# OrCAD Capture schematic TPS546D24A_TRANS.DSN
size Custom; title: TPS546D24A 2.95-V to 16-V, 40-A, up to 4× stackable; rev: 1.0; note: Datasheet: SLUSDN0        EVM: SLUUC47
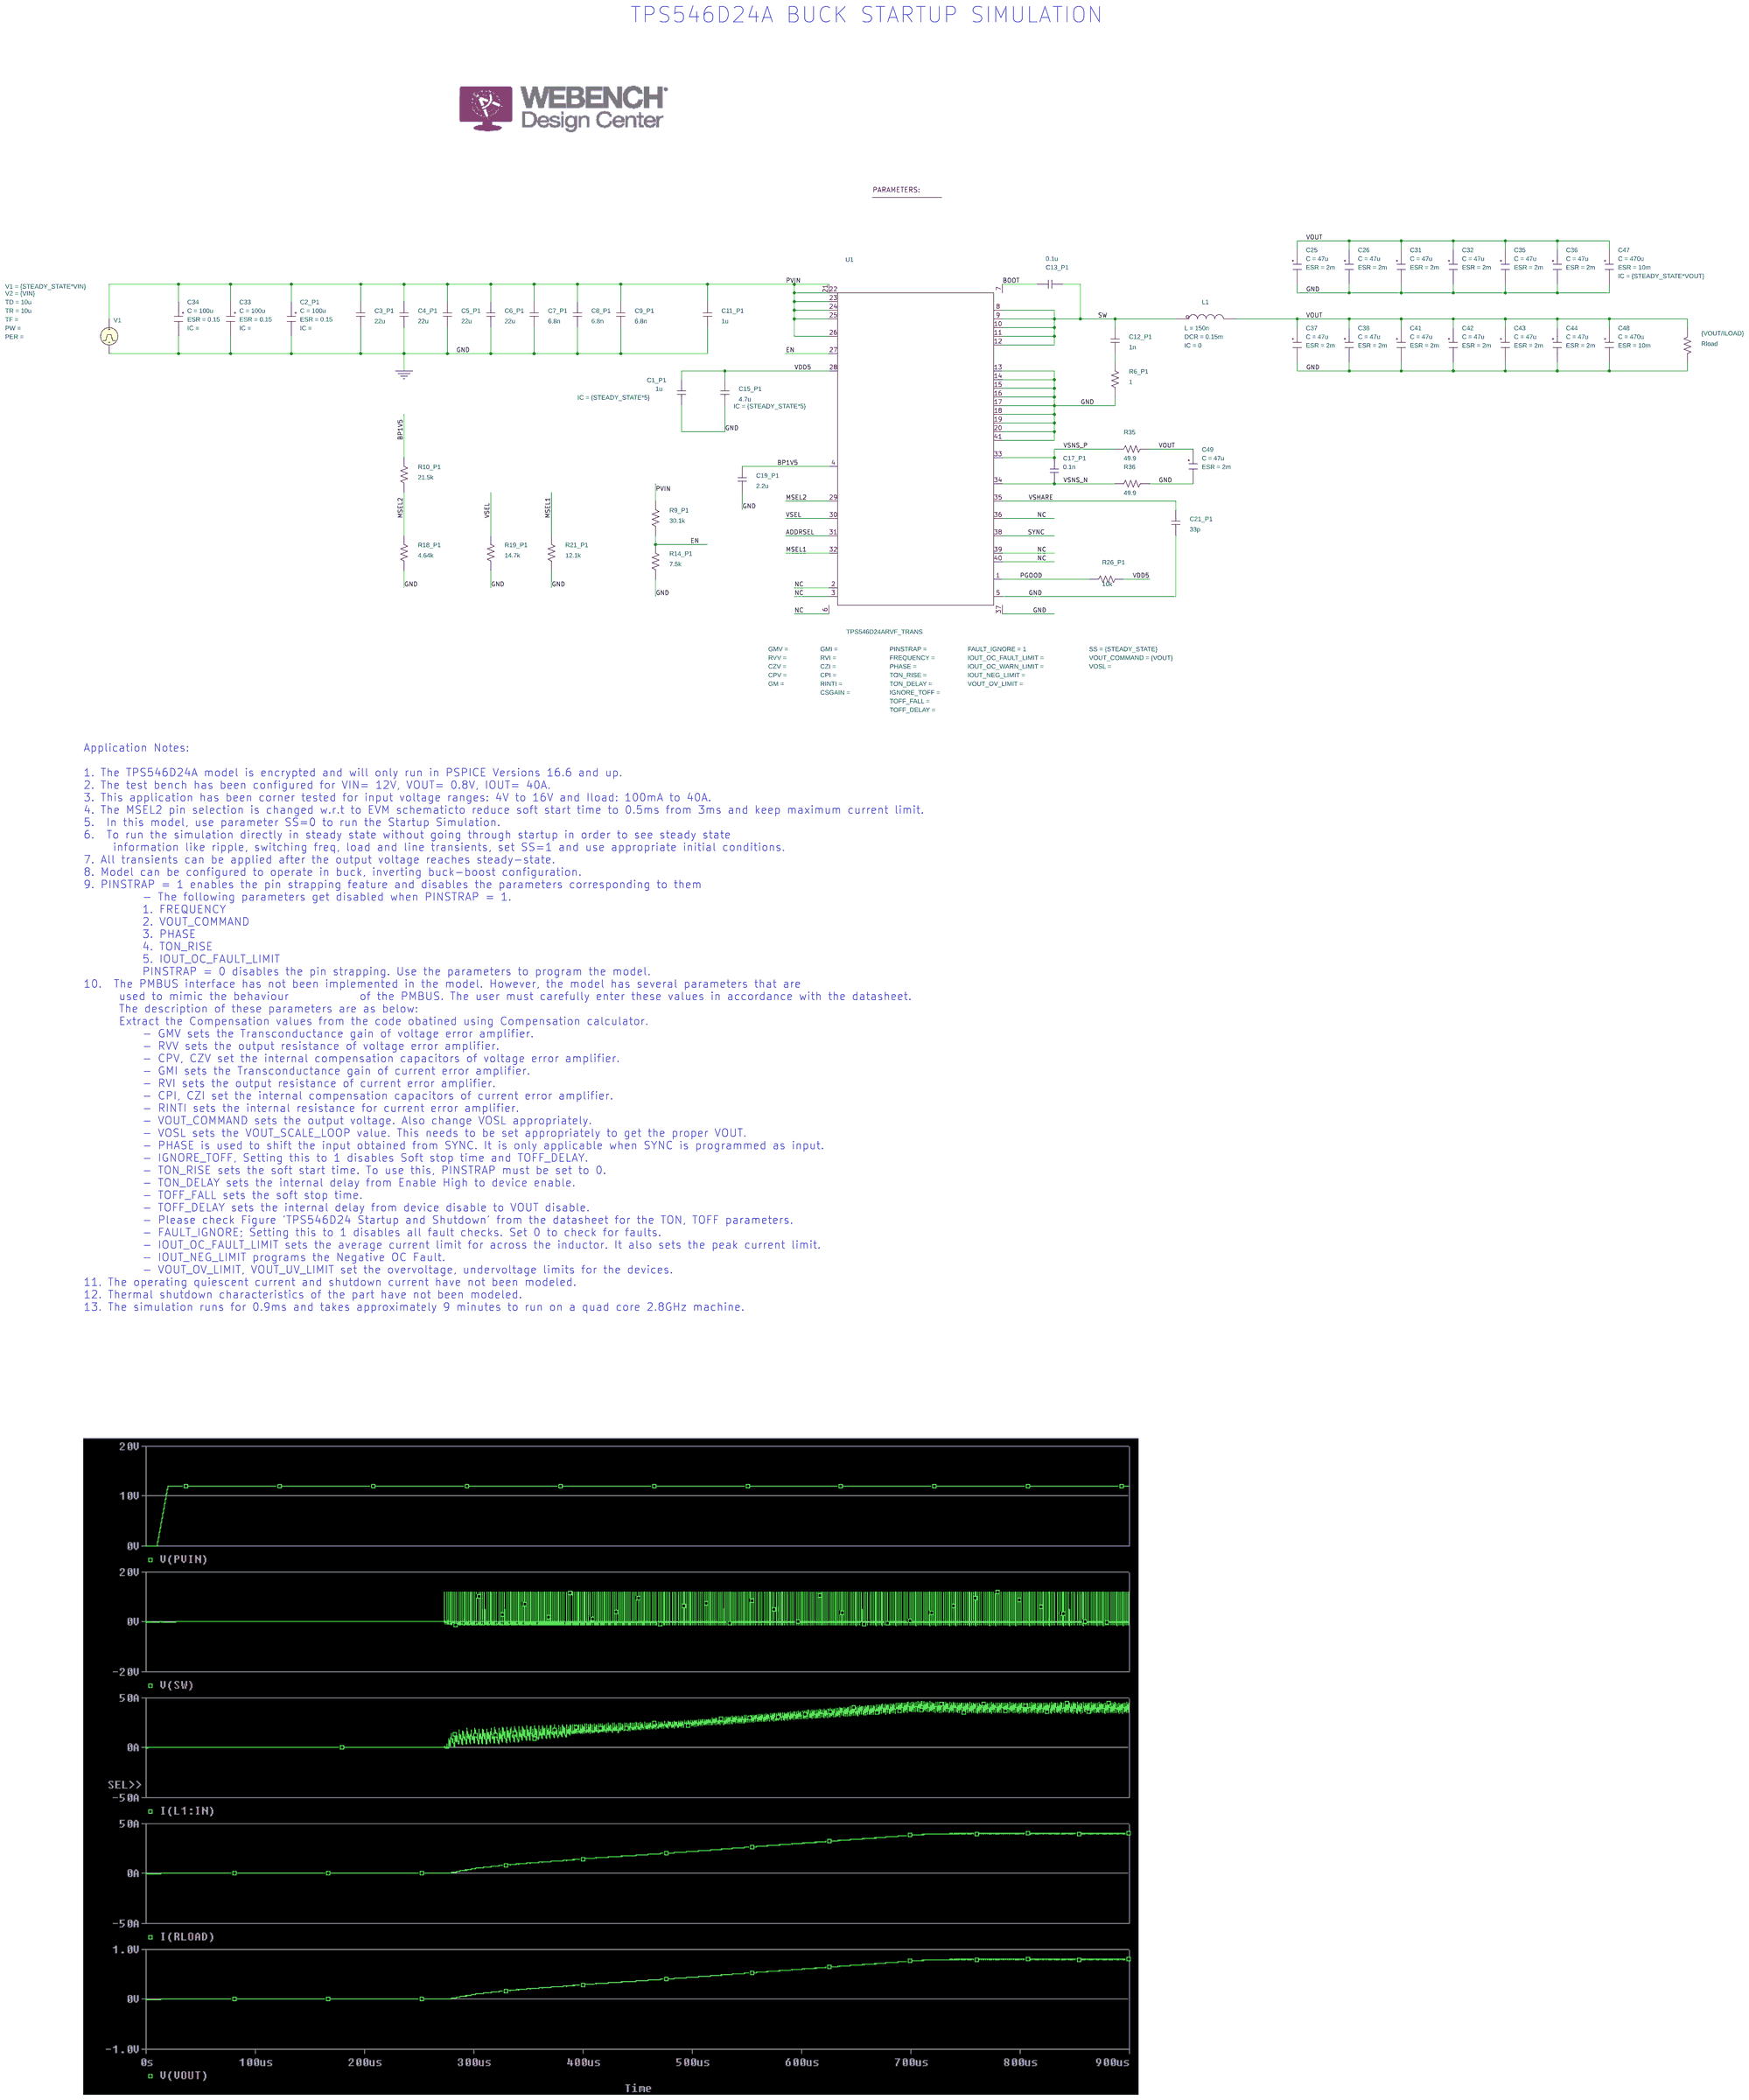
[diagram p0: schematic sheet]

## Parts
1  PARAM
C1_P1  1u  [RAD/CK05]
C2_P1  CESR
C3_P1  22u  [RAD/CK05]
C4_P1  22u  [RAD/CK05]
C5_P1  22u  [RAD/CK05]
C6_P1  22u  [RAD/CK05]
C7_P1  6.8n  [RAD/CK05]
C8_P1  6.8n  [RAD/CK05]
C9_P1  6.8n  [RAD/CK05]
C11_P1  1u  [RAD/CK05]
C12_P1  1n  [RAD/CK05]
C13_P1  0.1u  [RAD/CK05]
C15_P1  4.7u  [RAD/CK05]
C17_P1  0.1n  [RAD/CK05]
C19_P1  2.2u  [RAD/CK05]
C21_P1  33p  [RAD/CK05]
C25  CESR
C26  CESR
C31  CESR
C32  CESR
C33  CESR
C34  CESR
C35  CESR
C36  CESR
C37  CESR
C38  CESR
C41  CESR
C42  CESR
C43  CESR
C44  CESR
C47  CESR
C48  CESR
C49  CESR
L1  LDCR
R6_P1  1  [AX/RC05]
R9_P1  30.1k  [AX/RC05]
R10_P1  21.5k  [AX/RC05]
R14_P1  7.5k  [AX/RC05]
R18_P1  4.64k  [AX/RC05]
R19_P1  14.7k  [AX/RC05]
R21_P1  12.1k  [AX/RC05]
R26_P1  10k  [AX/RC05]
R35  49.9  [AX/RC05]
R36  49.9  [AX/RC05]
Rload  {VOUT/ILOAD}  [AX/RC05]
U1  TPS546D24ARVF_TRANS  [RVF0040A]
V1  VPULSE

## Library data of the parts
1 = PARAM: ILOAD: 40; STEADY_STATE: 0; VIN: 12; VOUT: 0.8
C1_P1 C15_P1 = C: IC: {STEADY_STATE*5}
C2_P1 C33 C34 = CESR_0: C: 100u; ESR: 0.15; PSpiceTemplate: X^@REFDES %IN %OUT @MODEL PARAMS:  ?C|C=@C||C=100u|  ?ESR|ESR=@ESR||ESR=0.01| ?X|X=@X||X=2|  ?IC|IC=@IC||IC=2|; X: 1
C3_P1 C4_P1 C5_P1 C6_P1 C7_P1 C8_P1 C9_P1 C11_P1 C12_P1 C13_P1 C17_P1 C19_P1 C21_P1 = C
C25 C26 C31 C32 C35-C38 C41-C44 C49 = CESR_0: C: 47u; ESR: 2m; IC: {STEADY_STATE*VOUT}; PSpiceTemplate: X^@REFDES %IN %OUT @MODEL PARAMS:  ?C|C=@C||C=100u|  ?ESR|ESR=@ESR||ESR=0.01| ?X|X=@X||X=2|  ?IC|IC=@IC||IC=2|; X: 1
C47 C48 = CESR_0: C: 470u; ESR: 10m; IC: {STEADY_STATE*VOUT}; PSpiceTemplate: X^@REFDES %IN %OUT @MODEL PARAMS:  ?C|C=@C||C=100u|  ?ESR|ESR=@ESR||ESR=0.01| ?X|X=@X||X=2|  ?IC|IC=@IC||IC=2|; X: 1
L1 = LDCR_1: DCR: 0.15m; IC: 0; L: 150n; PSpiceTemplate: X^@REFDES %IN %OUT @MODEL PARAMS:  ?L|L=@L||L=1u|  ?DCR|DCR=@DCR||DCR=0.01|  ?IC|IC=@IC||IC=0|
R6_P1 R9_P1 R10_P1 R14_P1 R18_P1 R19_P1 R21_P1 R26_P1 R35 R36 Rload = R
U1 = TPS546D24ARVF_TRANS: FAULT_IGNORE: 1; SS: {STEADY_STATE}; VOUT_COMMAND: {VOUT}
V1 = VPULSE: TD: 10u; TR: 10u; V1: {STEADY_STATE*VIN}; V2: {VIN}

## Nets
PVIN: C2_P1.1(IN) C3_P1.2 C4_P1.2 C5_P1.2 C6_P1.2 C7_P1.2 C8_P1.2 C9_P1.2 C11_P1.2 C33.1(IN) C34.1(IN) R9_P1.2 U1.21 U1.22 U1.23 U1.24 U1.25 U1.26 V1.1(+)
VDD5: C1_P1.1 C15_P1.2 R26_P1.2 U1.28
0: C1_P1.2 C2_P1.2(OUT) C3_P1.1 C4_P1.1 C5_P1.1 C6_P1.1 C7_P1.1 C8_P1.1 C9_P1.1 C11_P1.1 C15_P1.1 C19_P1.1 C21_P1.1 C25.2(OUT) C26.2(OUT) C31.2(OUT) C32.2(OUT) C33.2(OUT) C34.2(OUT) C35.2(OUT) C36.2(OUT) C37.2(OUT) C38.2(OUT) C41.2(OUT) C42.2(OUT) C43.2(OUT) C44.2(OUT) C47.2(OUT) C48.2(OUT) C49.2(OUT) R6_P1.1 R14_P1.1 R18_P1.1 R19_P1.1 R21_P1.1 R36.1 Rload.2 U1.5 U1.13 U1.14 U1.15 U1.16 U1.17 U1.18 U1.19 U1.20 U1.37 U1.41 V1.2(-)
ADDRSEL: U1.31
BOOT: C13_P1.1 U1.7
BP1V5: C19_P1.2 R10_P1.2 U1.4
EN: R9_P1.1 R14_P1.2 U1.27
MSEL1: R21_P1.2 U1.32
MSEL2: R10_P1.1 R18_P1.2 U1.29
NC: U1.2 U1.3 U1.6 U1.36 U1.39 U1.40
PGOOD: R26_P1.1 U1.1
SW: C12_P1.2 C13_P1.2 L1.1(IN) U1.8 U1.9 U1.10 U1.11 U1.12
SYNC: U1.38
VOUT: C25.1(IN) C26.1(IN) C31.1(IN) C32.1(IN) C35.1(IN) C36.1(IN) C37.1(IN) C38.1(IN) C41.1(IN) C42.1(IN) C43.1(IN) C44.1(IN) C47.1(IN) C48.1(IN) C49.1(IN) L1.3(OUT) R35.1 Rload.1
VSEL: R19_P1.2 U1.30
VSHARE: C21_P1.2 U1.35
VSNS_N: C17_P1.1 R36.2 U1.34
VSNS_P: C17_P1.2 R35.2 U1.33
N20990: C12_P1.1 R6_P1.2

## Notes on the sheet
- TPS546D24A BUCK STARTUP SIMULATION
- Application Notes:
  1. The TPS546D24A model is encrypted and will only run in PSPICE Versions 16.6 and up.
  2. The test bench has been configured for VIN= 12V, VOUT= 0.8V, IOUT= 40A.
  3. This application has been corner tested for input voltage ranges: 4V to 16V and Iload: 100mA to 40A.
  4. The MSEL2 pin selection is changed w.r.t to EVM schematicto reduce soft start time to 0.5ms from 3ms and keep maximum current limit.
  5.  In this model, use parameter SS=0 to run the Startup Simulation.
  6.  To run the simulation directly in steady state without going through startup in order to see steady state
       information like ripple, switching freq, load and line transients, set SS=1 and use appropriate initial conditions.
  7. All transients can be applied after the output voltage reaches steady-state.
  8. Model can be configured to operate in buck, inverting buck-boost configuration.
  9. PINSTRAP = 1 enables the pin strapping feature and disables the parameters corresponding to them
            - The following parameters get disabled when PINSTRAP = 1.
            1. FREQUENCY
            2. VOUT_COMMAND
            3. PHASE
            4. TON_RISE
            5. IOUT_OC_FAULT_LIMIT
            PINSTRAP = 0 disables the pin strapping. Use the parameters to program the model.
  10.  The PMBUS interface has not been implemented in the model. However, the model has several parameters that are
        used to mimic the behaviour	of the PMBUS. The user must carefully enter these values in accordance with the datasheet.
        The description of these parameters are as below:
        Extract the Compensation values from the code obatined using Compensation calculator.
            - GMV sets the Transconductance gain of voltage error amplifier.
            - RVV sets the output resistance of voltage error amplifier.
            - CPV, CZV set the internal compensation capacitors of voltage error amplifier.
            - GMI sets the Transconductance gain of current error amplifier.
            - RVI sets the output resistance of current error amplifier.
            - CPI, CZI set the internal compensation capacitors of current error amplifier.
            - RINTI sets the internal resistance for current error amplifier.
            - VOUT_COMMAND sets the output voltage. Also change VOSL appropriately.
            - VOSL sets the VOUT_SCALE_LOOP value. This needs to be set appropriately to get the proper VOUT.
            - PHASE is used to shift the input obtained from SYNC. It is only applicable when SYNC is programmed as input.
            - IGNORE_TOFF, Setting this to 1 disables Soft stop time and TOFF_DELAY.
            - TON_RISE sets the soft start time. To use this, PINSTRAP must be set to 0.
            - TON_DELAY sets the internal delay from Enable High to device enable.
            - TOFF_FALL sets the soft stop time.
            - TOFF_DELAY sets the internal delay from device disable to VOUT disable.
            - Please check Figure 'TPS546D24 Startup and Shutdown' from the datasheet for the TON, TOFF parameters.
            - FAULT_IGNORE; Setting this to 1 disables all fault checks. Set 0 to check for faults.
            - IOUT_OC_FAULT_LIMIT sets the average current limit for across the inductor. It also sets the peak current limit.
            - IOUT_NEG_LIMIT programs the Negative OC Fault.
            - VOUT_OV_LIMIT, VOUT_UV_LIMIT set the overvoltage, undervoltage limits for the devices.
  11. The operating quiescent current and shutdown current have not been modeled.
  12. Thermal shutdown characteristics of the part have not been modeled.
  13. The simulation runs for 0.9ms and takes approximately 9 minutes to run on a quad core 2.8GHz machine.
